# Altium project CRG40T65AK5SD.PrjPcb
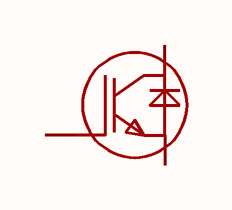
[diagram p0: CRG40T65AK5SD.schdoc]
1 sheet, 1 parts. Net scope: global (net labels, ports and power ports of the same name join across sheets).

## Sheet CRG40T65AK5SD.schdoc
size 127 x 101 mm

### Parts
Q?  crg40t65ak5sd  [TO-247-3_L15.9-W5.0-P5.44-L]  (value not drawn)

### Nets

Not connected (* = marked no-connect by the designer): Q? 1(G) 2(C) 3(E)

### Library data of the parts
Q? = crg40t65ak5sd: IGBT类型:FS(场截止);耗散功率(Pd):250W;集射极击穿电压(Vces):650V;集电极电流(Ic):80A;; Manufacturer: CRMICRO(华润微); AddInBom: yes; ModelId: 06d11a66e67643458860efec572770e6; ModelTransform: 625.983,196.85,0,0,0,0,0,5.906,-196.85; Pd - Power Dissipation: 250W; Collector-Emitter Breakdown Voltage (Vces): 650V; Current - Collector(Ic): 80A; Current - Collector Pulsed (Icm): 160A; Vce Saturation(VCE(sat)): 1.8V@40A,15V; Gate-Emitter Threshold Voltage (Vge(th)@Ic): 3.5V；6.5V; Gate Charge(Qg): 97nC; Input Capacitance(Cies): 2.798nF@30V; Output Capacitance(Coes): 166pF; Reverse Transfer Capacitance (Cres): 16pF; Td(on): 52ns; Td(off): 185ns; Turn-On Energy (Eon): 1.35mJ; Switching Energy(Eoff): 820uJ; Reverse Recovery Time(trr): 48ns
